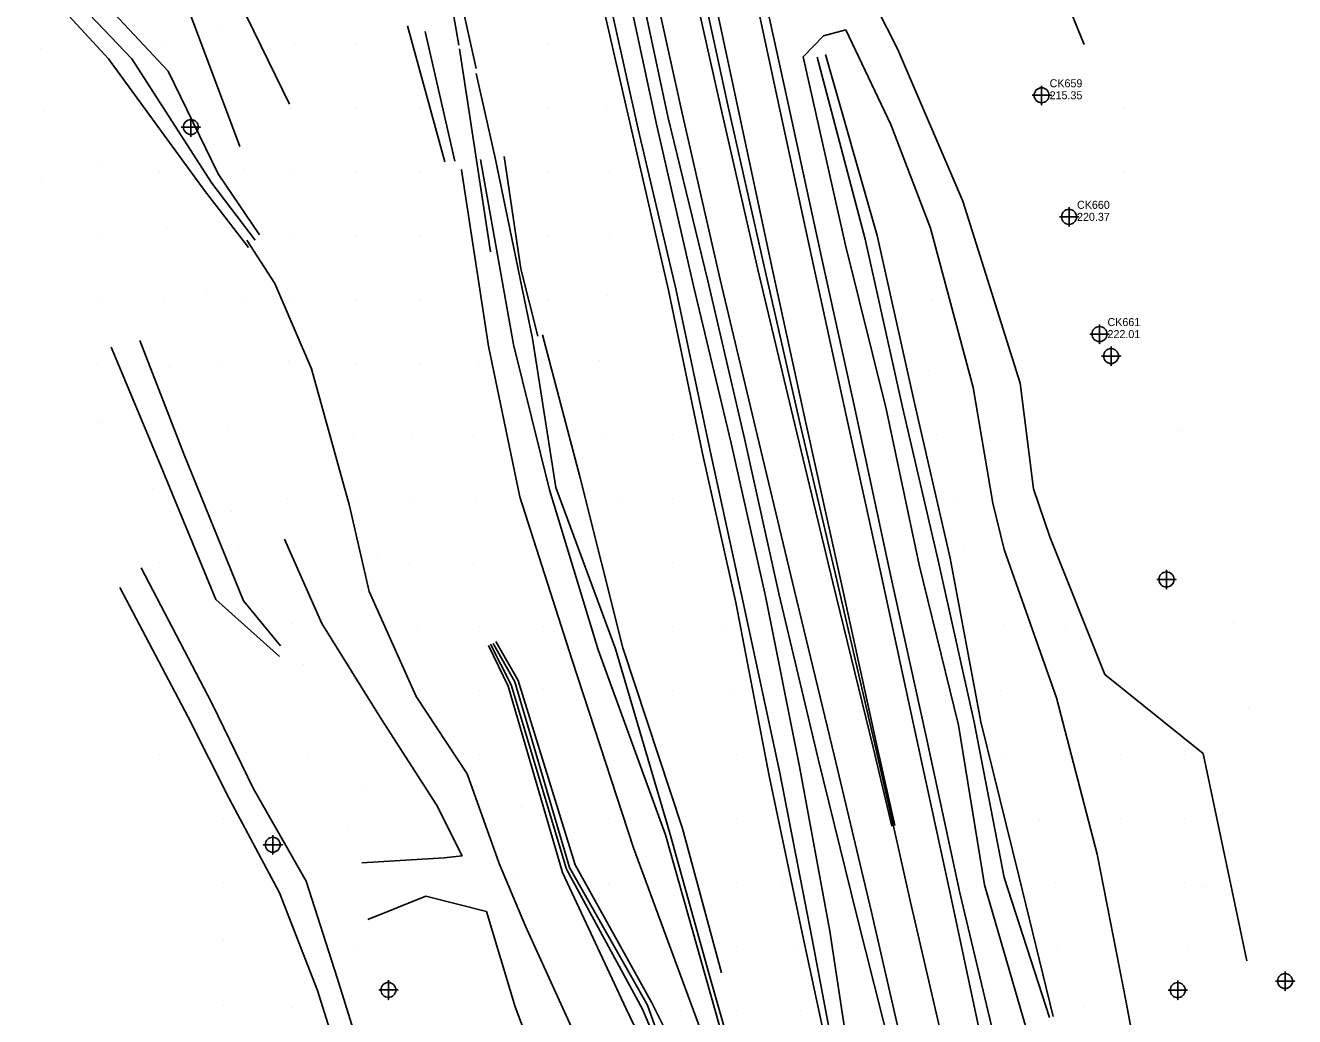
# Model space of a CAD drawing. Extents: x 1941547 to 1942851, y 663002 to 668358.
# Drawn here: x 1941884.2 to 1942280.5, y 665902.5 to 666212 of the extents above; entities that cross this region are included whole.
import ezdxf

# ---------------------------------------------------------------- set-up
doc = ezdxf.new("R2010")
doc.units = 0
for name, color, linetype in [('CTL GPS Vertical Cogo Elevation', 7, 'Continuous'), ('CTL NGS Vertical CELL', 7, 'Continuous'), ('Exist DTM Drainline Cogo Elevation', 7, 'Continuous'), ('Exist Property Iron Pin Cogo Number', 7, 'Continuous'), ('Exist Roads EOP Cogo Point CELL', 7, 'Continuous'), ('Exist Roads EOT', 7, 'Continuous'), ('Exist Roads Soil', 7, 'Continuous'), ('Exist Utilities Telephone UG Cable SUE LOS C Cogo Elevation', 7, 'Continuous'), ('Exist Utilities Telephone UG FO SUE LOS C Cogo Elevation', 7, 'Continuous'), ('PH Exist DTM Point', 7, 'Continuous')]:
    doc.layers.add(name, color=color, linetype=linetype)

msp = doc.modelspace()

# ---------------------------------------------------------------- linework, layer by layer
at = {"layer": 'CTL NGS Vertical CELL'}
for p, q in [((1942083.98, 665890.54), (1942078.49, 665906.03)), ((1942082.98, 665890.41), (1942076.86, 665904.78))]:
    msp.add_line(p, q, dxfattribs=at)
for points in [[(1942137.2, 665888.17), (1942129.75, 665927.19), (1942119.82, 665978.57), (1942108.24, 666032.34), (1942098.02, 666079.16), (1942087.31, 666129.73), (1942075.59, 666179.6), (1942064.03, 666231.55), (1942052.46, 666280.06), (1942040, 666332.34), (1942027.67, 666382.39), (1942014.48, 666434.14), (1942001.98, 666485.22)], [(1942135.5, 665887.91), (1942127.19, 665926.67), (1942116.47, 665977.64), (1942106.06, 666031.75), (1942095.67, 666078.28), (1942084.99, 666129.32), (1942073.59, 666178.98), (1942061.57, 666231.07), (1942050.7, 666279.83), (1942038.07, 666332.06), (1942025.94, 666381.57), (1942012.73, 666433.79), (1941999.93, 666484.44)], [(1942131.46, 666202.11), (1942146.41, 666145.19), (1942158.08, 666092.78), (1942169.26, 666044.9), (1942180.44, 665994.38), (1942189.83, 665945.88), (1942204.05, 665902.19)], [(1942134.06, 666202.94), (1942150.19, 666146.42), (1942161.91, 666093.64), (1942173.03, 666045.64), (1942182.56, 665994.48), (1942194.43, 665946.47), (1942205.12, 665902.54)], [(1942076.86, 665904.78), (1942053.13, 665948.54), (1942035.85, 666006.08), (1942029.46, 666018.76)], [(1942078.49, 665906.03), (1942054.12, 665948.97), (1942036.99, 666007), (1942030.23, 666018.99)]]:
    msp.add_lwpolyline(points, dxfattribs=at)
at = {"layer": 'Exist DTM Drainline Cogo Elevation'}
for points in [[(1942201.54, 666193.17), (1942201.54, 666187.17), (1942201.54, 666190.17), (1942204.54, 666190.17), (1942198.54, 666190.17)], [(1942201.54, 666193.17), (1942201.54, 666187.17), (1942201.54, 666190.17), (1942204.54, 666190.17), (1942198.54, 666190.17)], [(1941935.88, 666183.26), (1941935.88, 666177.26), (1941935.88, 666180.26), (1941938.88, 666180.26), (1941932.88, 666180.26)], [(1942210.1, 666155.21), (1942210.1, 666149.21), (1942210.1, 666152.21), (1942213.1, 666152.21), (1942207.1, 666152.21)], [(1942210.1, 666155.21), (1942210.1, 666149.21), (1942210.1, 666152.21), (1942213.1, 666152.21), (1942207.1, 666152.21)], [(1942219.62, 666118.6), (1942219.62, 666112.6), (1942219.62, 666115.6), (1942222.62, 666115.6), (1942216.62, 666115.6)], [(1942219.62, 666118.6), (1942219.62, 666112.6), (1942219.62, 666115.6), (1942222.62, 666115.6), (1942216.62, 666115.6)], [(1942223.21, 666111.73), (1942223.21, 666105.73), (1942223.21, 666108.73), (1942226.21, 666108.73), (1942220.21, 666108.73)], [(1942240.53, 666041.97), (1942240.53, 666035.97), (1942240.53, 666038.97), (1942243.53, 666038.97), (1942237.53, 666038.97)], [(1941961.44, 665959.14), (1941961.44, 665953.14), (1941961.44, 665956.14), (1941964.44, 665956.14), (1941958.44, 665956.14)], [(1942277.55, 665916.55), (1942277.55, 665910.55), (1942277.55, 665913.55), (1942280.55, 665913.55), (1942274.55, 665913.55)], [(1941997.54, 665913.79), (1941997.54, 665907.79), (1941997.54, 665910.79), (1942000.54, 665910.79), (1941994.54, 665910.79)], [(1942244.03, 665913.72), (1942244.03, 665907.72), (1942244.03, 665910.72), (1942247.03, 665910.72), (1942241.03, 665910.72)]]:
    msp.add_lwpolyline(points, dxfattribs=at)
for centre in [(1942201.54, 666190.17), (1942201.54, 666190.17), (1941935.88, 666180.26), (1942210.1, 666152.21), (1942210.1, 666152.21), (1942219.62, 666115.6), (1942219.62, 666115.6), (1942223.21, 666108.73), (1942240.53, 666038.97), (1941961.44, 665956.14), (1942277.55, 665913.55), (1941997.54, 665910.79), (1942244.03, 665910.72)]:
    msp.add_circle(centre, 2.34, dxfattribs=at)
at = {"layer": 'Exist Property Iron Pin Cogo Number'}
msp.add_lwpolyline([(1942228.27, 665631.91), (1942215.35, 665690.54), (1942203.38, 665744.37), (1942193.36, 665791.05), (1942181.96, 665842.56), (1942170.96, 665893.33), (1942160.58, 665938.17), (1942155.29, 665961.96), (1942149.62, 665986.57), (1942137.61, 666038.72), (1942126.12, 666087.51), (1942115.02, 666136.31), (1942103.6, 666187.08), (1942093.09, 666235.61), (1942082.3, 666286.44), (1942071.51, 666338.53), (1942065.4, 666365.11), (1942061.56, 666389.7), (1942049.68, 666441.21), (1942041.5, 666492.09), (1942031.83, 666544.21), (1942023.2, 666595.06), (1942013.62, 666656.61), (1942008.43, 666689.96)], dxfattribs=at)
at = {"layer": 'Exist Roads EOT'}
for points in [[(1942239.89, 665634.47), (1942227.05, 665692.43), (1942215.28, 665746.03), (1942204.9, 665793.1), (1942193.81, 665844.48), (1942182.41, 665896.46), (1942173.11, 665940.53), (1942162.51, 665989.38), (1942151.29, 666040.92), (1942140.43, 666090.67), (1942129.8, 666139.39), (1942119.07, 666189.07), (1942108.58, 666238.14), (1942097.82, 666289.68), (1942077.07, 666393.11), (1942067.43, 666444.43), (1942058.06, 666495.58), (1942049.26, 666547.02), (1942041.05, 666598.14), (1942031.78, 666658.51), (1942026.7, 666693.35)], [(1942216.33, 665631.64), (1942203.63, 665688.68), (1942191.56, 665741.16), (1942181.15, 665788.55), (1942170.15, 665839.04), (1942158.52, 665891.09), (1942148.46, 665935.11), (1942136.79, 665984.14), (1942124.38, 666035.44), (1942112.67, 666084.11), (1942101.18, 666132.69), (1942089.27, 666184.63), (1942078.82, 666232.22), (1942067.51, 666283.26), (1942056.28, 666335.48), (1942045.64, 666385.95), (1942034.6, 666439.01), (1942024.01, 666491.71), (1942014.76, 666541.49), (1942006.11, 666591.53), (1942001.31, 666620.24), (1941993.82, 666637.67), (1941979.79, 666649.91), (1941961.73, 666657.29)], [(1942154.73, 665961.88), (1942148.9, 665986.47), (1942136.37, 666038.07), (1942124.51, 666087.33), (1942112.95, 666135.81), (1942101.29, 666186.74), (1942090.44, 666235.06), (1942079.42, 666285.53), (1942068.09, 666338.16), (1942062.34, 666365.05), (1942057.42, 666388.45), (1942046.52, 666440.57), (1942036.47, 666490.47), (1942026.54, 666543.55), (1942017.93, 666593.73), (1942007.82, 666655.78)], [(1942155.67, 665962.14), (1942150.22, 665986.74), (1942138.88, 666038.57), (1942127.93, 666087.9), (1942117.32, 666136.64), (1942106.41, 666187.82), (1942095.96, 666236.54), (1942085.34, 666286.97), (1942074.48, 666339.36), (1942068.19, 666365.82)]]:
    msp.add_lwpolyline(points, dxfattribs=at)
at = {"layer": 'Exist Roads Soil'}
for points in [[(1942126.83, 665824.77), (1942111.91, 665871.48), (1942102.3, 665894.79), (1942084.11, 665959.22), (1942063.03, 666017.01), (1942047.89, 666066.94), (1942036.65, 666112.3), (1942026.34, 666170.14)], [(1942121.5, 665821.77), (1942105.8, 665869.03), (1942074.08, 665955.18), (1942054.97, 666013.72), (1942038.57, 666064.82), (1942028.79, 666111.83), (1942020.41, 666166.91), (1942020.43, 666166.74)], [(1941920.31, 666042.64), (1941942.38, 666000.34), (1941955.44, 665973.58), (1941971.89, 665944.72), (1941981.51, 665914.54), (1941997.6, 665863.12), (1942002.18, 665835.77), (1942012.27, 665799.49), (1942018.28, 665767.8), (1942026.41, 665723.95), (1942035.82, 665683.01), (1942049.69, 665651.71), (1942061.21, 665618.05), (1942066.65, 665579.13)], [(1941913.66, 666036.51), (1941935.03, 665995.96), (1941947.89, 665970.4), (1941963.56, 665941.14), (1941975.45, 665910.61), (1941990.79, 665861.46), (1941995.66, 665834.61), (1942004.42, 665797.14), (1942010.19, 665767.15), (1942019.69, 665721.78), (1942028.17, 665681.25), (1942042.18, 665649.99), (1942053.95, 665616.39), (1942058.52, 665576.7)]]:
    msp.add_lwpolyline(points, dxfattribs=at)
at = {"layer": 'Exist Utilities Telephone UG Cable SUE LOS C Cogo Elevation'}
for points in [[(1942241.99, 665634.93), (1942229.18, 665693.32), (1942218.46, 665746.7), (1942209.27, 665793.91), (1942197.95, 665845.25), (1942186.36, 665897.34), (1942176.03, 665941.11), (1942165.47, 665989.95), (1942154.18, 666041.36), (1942143.37, 666091.41), (1942132.79, 666139.63), (1942122, 666189.48), (1942111.14, 666238.84), (1942100.41, 666290.27), (1942079.89, 666393.87), (1942070.21, 666444.86), (1942060.95, 666496.14), (1942052.29, 666547.35), (1942044.06, 666598.94), (1942035.22, 666658.38), (1942029.81, 666693.65)], [(1942213.99, 665632.37), (1942202.16, 665688.24), (1942190.02, 665740.92), (1942178.65, 665787.73), (1942166.53, 665839.16), (1942154.86, 665890.17), (1942143.77, 665934.31), (1942131.73, 665982.91), (1942119.44, 666034.59), (1942108.8, 666082.94), (1942097.26, 666132.24), (1942084.85, 666183.55), (1942074.65, 666231.51), (1942063.8, 666282.56), (1942052.72, 666333.95), (1942042.01, 666385.23), (1942031.54, 666438.14), (1942020.1, 666490.97), (1942010.35, 666540.81), (1942001.86, 666591.1), (1941996.76, 666619.63), (1941991.94, 666636.36), (1941978.98, 666647.81), (1941961.64, 666654.67)]]:
    msp.add_lwpolyline(points, dxfattribs=at)
at = {"layer": 'Exist Utilities Telephone UG FO SUE LOS C Cogo Elevation'}
for p, q in [((1942025.01, 666198.49), (1942016.74, 666235.33)), ((1942003.48, 666211.82), (1942015.2, 666169.38)), ((1942008.99, 666210.14), (1942018.3, 666169.6)), ((1942030.93, 666170.6), (1942024.95, 666196.97)), ((1942038.93, 666135.99), (1942033.69, 666171.04)), ((1942086.97, 665892.44), (1942079.79, 665906.78)), ((1942079.6, 665888.69), (1942071.84, 665904.91))]:
    msp.add_line(p, q, dxfattribs=at)
for points in [[(1942040.06, 666695.59), (1942044.64, 666660.9), (1942053.37, 666600.34), (1942061.1, 666549.68), (1942070.22, 666496.32), (1942078.82, 666447.64), (1942091.81, 666396.73), (1942107.09, 666347.46), (1942120.54, 666292.55), (1942121.58, 666285.4), (1942136.04, 666246.7), (1942142.99, 666231.38), (1942156.51, 666204.69), (1942176.98, 666157.07), (1942194.89, 666100.26)], [(1942168.3, 665779.55), (1942157.65, 665834.34), (1942151.92, 665851.93), (1942141.5, 665888.6), (1942135.45, 665929.19), (1942125.9, 665980.59), (1942115.36, 666033.71), (1942104.57, 666081.51), (1942092.84, 666130.71), (1942081.31, 666181.18), (1942070.23, 666232.6), (1942059.43, 666281.93), (1942047.77, 666333.59), (1942037.49, 666384.47), (1942022.61, 666435.89), (1942012.32, 666487.89)], [(1942019.56, 666205.82), (1942013.89, 666238.19), (1942002.78, 666304.16), (1941996.3, 666343.72)], [(1941917.76, 666272.82), (1941946.71, 666228.46), (1941966.64, 666187.4)], [(1942214.84, 666205.98), (1942198.8, 666245.36), (1942187.02, 666258.54)], [(1941957.32, 666146.58), (1941944.42, 666165.6), (1941928.81, 666197.73), (1941884.45, 666245.12)], [(1941923.31, 666244.71), (1941935.16, 666216.93), (1941951.19, 666174.18)], [(1941955.97, 666144.9), (1941942.43, 666162.7), (1941917.43, 666201.51), (1941884.35, 666236.32)], [(1941953.92, 666142.62), (1941940.16, 666160.4), (1941910.19, 666201.54), (1941884.2, 666229.78)], [(1942140.41, 666210.58), (1942133.48, 666208.77), (1942127.11, 666202.22), (1942140.27, 666143.4), (1942153.02, 666092.23), (1942163.33, 666043.55), (1942175.57, 665993.45), (1942183.72, 665943.62), (1942196.71, 665898.83), (1942195.59, 665899.62), (1942206.59, 665842.7), (1942218.92, 665796.29)], [(1942140.41, 666210.58), (1942154.45, 666181), (1942166.81, 666148.7), (1942180.19, 666098.88)], [(1942019.8, 666204.63), (1942029.48, 666141.27)], [(1942103.53, 665895.22), (1942097.95, 665914.86), (1942085.48, 665959.77), (1942068.43, 666017.32), (1942049.81, 666067.68), (1942042.57, 666114.26), (1942030.93, 666170.6)], [(1941953.31, 666144.9), (1941962.09, 666131.4), (1941973.53, 666104.71), (1941985.36, 666061.95), (1941991.55, 666035.22), (1942006.18, 666002.41), (1942022.13, 665978.29), (1942032.16, 665950.27), (1942040.41, 665930.66), (1942055.12, 665898.26), (1942076.62, 665854.83)], [(1942038.93, 666135.99), (1942044.18, 666114.93)], [(1941919.97, 666113.62), (1941933.81, 666077.93), (1941952.27, 666032.29), (1941963.85, 666018.28)], [(1942101.61, 665916.15), (1942089.35, 665961.21), (1942070.77, 666017.62), (1942057.49, 666070.68), (1942045.66, 666115.34)], [(1941910.94, 666111.54), (1941926.39, 666074.65), (1941943.72, 666032.73), (1941963.5, 666014.94)], [(1942194.89, 666100.26), (1942199.04, 666067.28), (1942204.12, 666052.25), (1942221.27, 666009.31), (1942251.98, 665984.6), (1942265.62, 665919.92)], [(1942180.19, 666098.88), (1942186.34, 666062.84), (1942189.8, 666048.29), (1942206.14, 666002.05), (1942218.91, 665953.16), (1942227.93, 665906.98), (1942237.59, 665854.67)], [(1941965.07, 666051.51), (1941976.81, 666025.18), (1941995.32, 665995.48), (1942012.62, 665968.62), (1942020.56, 665952.62), (1942015.02, 665952), (1941989.28, 665950.51)], [(1942071.84, 665904.91), (1942051.95, 665947.48), (1942034.94, 666005.65), (1942028.8, 666018.35)], [(1942079.79, 665906.78), (1942055.92, 665949.89), (1942038.03, 666007.43), (1942031.08, 666019.55)], [(1941991.1, 665932.77), (1942009.28, 665940.05), (1942028.18, 665935.24), (1942037.16, 665905.54), (1942042.74, 665890.66), (1942053.72, 665846.75)]]:
    msp.add_lwpolyline(points, dxfattribs=at)
at = {"layer": 'PH Exist DTM Point'}
for p, q in [((1941945.56, 666210.58), (1941945.56, 666210.58)), ((1941889.24, 666204.85), (1941889.24, 666204.85)), ((1941927.96, 666205.96), (1941927.96, 666205.96)), ((1941968.14, 666206.02), (1941968.14, 666206.02)), ((1941987.13, 666205.95), (1941987.13, 666205.95)), ((1942005.99, 666205.87), (1942005.99, 666205.87)), ((1942018.05, 666206.81), (1942018.05, 666206.81)), ((1942047.13, 666205.95), (1942047.13, 666205.95)), ((1941890.05, 666185.52), (1941890.05, 666185.52)), ((1941947.51, 666185.58), (1941947.51, 666185.58)), ((1941967.13, 666185.95), (1941967.13, 666185.95)), ((1941987.13, 666185.95), (1941987.13, 666185.95)), ((1942007.13, 666185.95), (1942007.13, 666185.95)), ((1942047.13, 666185.95), (1942047.13, 666185.95)), ((1942065.61, 666185.85), (1942065.61, 666185.85)), ((1942227.13, 666185.95), (1942227.13, 666185.95)), ((1941907.1, 666169.35), (1941907.1, 666169.35)), ((1941925.99, 666166.37), (1941925.99, 666166.37)), ((1941952.74, 666166.94), (1941952.74, 666166.94)), ((1941967.13, 666165.95), (1941967.13, 666165.95)), ((1941987.13, 666165.95), (1941987.13, 666165.95)), ((1942007.13, 666165.95), (1942007.13, 666165.95)), ((1942047.13, 666165.95), (1942047.13, 666165.95)), ((1942066.75, 666165.92), (1942066.75, 666165.92)), ((1942227.13, 666165.95), (1942227.13, 666165.95)), ((1941889.14, 666163.34), (1941889.14, 666163.34)), ((1941928.13, 666148.52), (1941928.13, 666148.52)), ((1941907.01, 666145.94), (1941907.01, 666145.94)), ((1941967.13, 666145.95), (1941967.13, 666145.95)), ((1941987.13, 666145.95), (1941987.13, 666145.95)), ((1942007.13, 666145.95), (1942007.13, 666145.95)), ((1942047.13, 666145.95), (1942047.13, 666145.95)), ((1942066.61, 666145.91), (1942066.61, 666145.91)), ((1941940.77, 666129.23), (1941940.77, 666129.23)), ((1941907.15, 666125.95), (1941907.15, 666125.95)), ((1941927.65, 666125.83), (1941927.65, 666125.83)), ((1941953.05, 666126.22), (1941953.05, 666126.22)), ((1941967.13, 666125.95), (1941967.13, 666125.95)), ((1941987.13, 666125.95), (1941987.13, 666125.95)), ((1942007.13, 666125.95), (1942007.13, 666125.95)), ((1942047.13, 666125.95), (1942047.13, 666125.95)), ((1942065.63, 666127.66), (1942065.63, 666127.66)), ((1942167.13, 666125.95), (1942167.13, 666125.95)), ((1941906.77, 666106.09), (1941906.77, 666106.09)), ((1941929.17, 666105.45), (1941929.17, 666105.45)), ((1941945.58, 666105.85), (1941945.58, 666105.85)), ((1941966.5, 666107.18), (1941966.5, 666107.18)), ((1941987.13, 666105.95), (1941987.13, 666105.95)), ((1942007.13, 666105.95), (1942007.13, 666105.95)), ((1942025.8, 666105.86), (1942025.8, 666105.86)), ((1942063.46, 666107.34), (1942063.46, 666107.34)), ((1942166.14, 666104.21), (1942166.14, 666104.21)), ((1941906.93, 666087.74), (1941906.93, 666087.74)), ((1941947.23, 666085.95), (1941947.23, 666085.95)), ((1942168.64, 666084.38), (1942168.64, 666084.38)), ((1942245.24, 666085.33), (1942245.24, 666085.33)), ((1941986.69, 666084.25), (1941986.69, 666084.25)), ((1942005.14, 666084.14), (1942005.14, 666084.14)), ((1942024.05, 666084.06), (1942024.05, 666084.06)), ((1942065.28, 666084.15), (1942065.28, 666084.15)), ((1942086.14, 666084.21), (1942086.14, 666084.21)), ((1941924.17, 666067.23), (1941924.17, 666067.23)), ((1942070.27, 666064.5), (1942070.27, 666064.5)), ((1941966.14, 666064.21), (1941966.14, 666064.21)), ((1941988.01, 666064.34), (1941988.01, 666064.34)), ((1942004.56, 666064.14), (1942004.56, 666064.14)), ((1942024.73, 666064.11), (1942024.73, 666064.11)), ((1942086.14, 666064.21), (1942086.14, 666064.21)), ((1942174.38, 666063.75), (1942174.38, 666063.75)), ((1941948.65, 666060.31), (1941948.65, 666060.31)), ((1941950.89, 666048.24), (1941950.89, 666048.24)), ((1941994.27, 666045.69), (1941994.27, 666045.69)), ((1942177.36, 666048.32), (1942177.36, 666048.32)), ((1941926.14, 666044.21), (1941926.14, 666044.21)), ((1942004.12, 666044.05), (1942004.12, 666044.05)), ((1942024.02, 666043.74), (1942024.02, 666043.74)), ((1942086.14, 666044.21), (1942086.14, 666044.21)), ((1941967.35, 666025.22), (1941967.35, 666025.22)), ((1942261.52, 666025.67), (1942261.52, 666025.67)), ((1942006.76, 666024.25), (1942006.76, 666024.25)), ((1942026.14, 666024.21), (1942026.14, 666024.21)), ((1942046.14, 666024.21), (1942046.14, 666024.21)), ((1942086.14, 666024.21), (1942086.14, 666024.21)), ((1942102.7, 666023.54), (1942102.7, 666023.54)), ((1942190, 666024.48), (1942190, 666024.48)), ((1942208.88, 666024.4), (1942208.88, 666024.4)), ((1941971.07, 666012.42), (1941971.07, 666012.42)), ((1942026.14, 666004.21), (1942026.14, 666004.21)), ((1942045.81, 666004.81), (1942045.81, 666004.81)), ((1942086.14, 666004.21), (1942086.14, 666004.21)), ((1942104.26, 666003.55), (1942104.26, 666003.55)), ((1942188.75, 666004.39), (1942188.75, 666004.39)), ((1941989.22, 665999), (1941989.22, 665999)), ((1942266.23, 665998.91), (1942266.23, 665998.91)), ((1941926.13, 665984.32), (1941926.13, 665984.32)), ((1941972.7, 665984.44), (1941972.7, 665984.44)), ((1942026.14, 665984.21), (1942026.14, 665984.21)), ((1942106.14, 665984.21), (1942106.14, 665984.21)), ((1942190.2, 665984.49), (1942190.2, 665984.49)), ((1942226.14, 665984.21), (1942226.14, 665984.21)), ((1942246.14, 665984.21), (1942246.14, 665984.21)), ((1941990.52, 665973.85), (1941990.52, 665973.85)), ((1942039.03, 665968.15), (1942039.03, 665968.15)), ((1941946.14, 665964.21), (1941946.14, 665964.21)), ((1942066.14, 665964.21), (1942066.14, 665964.21)), ((1942106.14, 665964.21), (1942106.14, 665964.21)), ((1942200.81, 665963.83), (1942200.81, 665963.83)), ((1942226.14, 665964.21), (1942226.14, 665964.21)), ((1942246.14, 665964.21), (1942246.14, 665964.21)), ((1941984.93, 665961), (1941984.93, 665961)), ((1942037.85, 665945.72), (1942037.85, 665945.72)), ((1941946.14, 665944.21), (1941946.14, 665944.21)), ((1942066.17, 665943.72), (1942066.17, 665943.72)), ((1942106.14, 665944.21), (1942106.14, 665944.21)), ((1942120.72, 665944.41), (1942120.72, 665944.41)), ((1942205.99, 665944.2), (1942205.99, 665944.2)), ((1942246.13, 665944.28), (1942246.13, 665944.28)), ((1942251.92, 665942.73), (1942251.92, 665942.73)), ((1941945.96, 665926.67), (1941945.96, 665926.67)), ((1941987.87, 665924.33), (1941987.87, 665924.33)), ((1942106.14, 665924.21), (1942106.14, 665924.21)), ((1942124.27, 665924.39), (1942124.27, 665924.39)), ((1942206.4, 665924.22), (1942206.4, 665924.22)), ((1942246.95, 665924.32), (1942246.95, 665924.32)), ((1941946.1, 665905.96), (1941946.1, 665905.96)), ((1941967.52, 665905.39), (1941967.52, 665905.39)), ((1942088.72, 665904.4), (1942088.72, 665904.4)), ((1942106.14, 665904.21), (1942106.14, 665904.21)), ((1942126.14, 665904.21), (1942126.14, 665904.21)), ((1942214.75, 665905.76), (1942214.75, 665905.76))]:
    msp.add_line(p, q, dxfattribs=at)

# ---------------------------------------------------------------- texts
at = {"layer": 'CTL GPS Vertical Cogo Elevation'}
for s, p in [('CK659', (1942204.04, 666192.67)), ('CK660', (1942212.6, 666154.71)), ('CK661', (1942222.12, 666118.1))]:
    msp.add_text(s, height=2.5, dxfattribs=at).set_placement(p)
at = {"layer": 'Exist Roads EOP Cogo Point CELL'}
for s, p in [('215.35', (1942204.04, 666188.92)), ('220.37', (1942212.6, 666150.96)), ('222.01', (1942222.12, 666114.35))]:
    msp.add_text(s, height=2.5, dxfattribs=at).set_placement(p)

doc.saveas('drawing.dxf')
